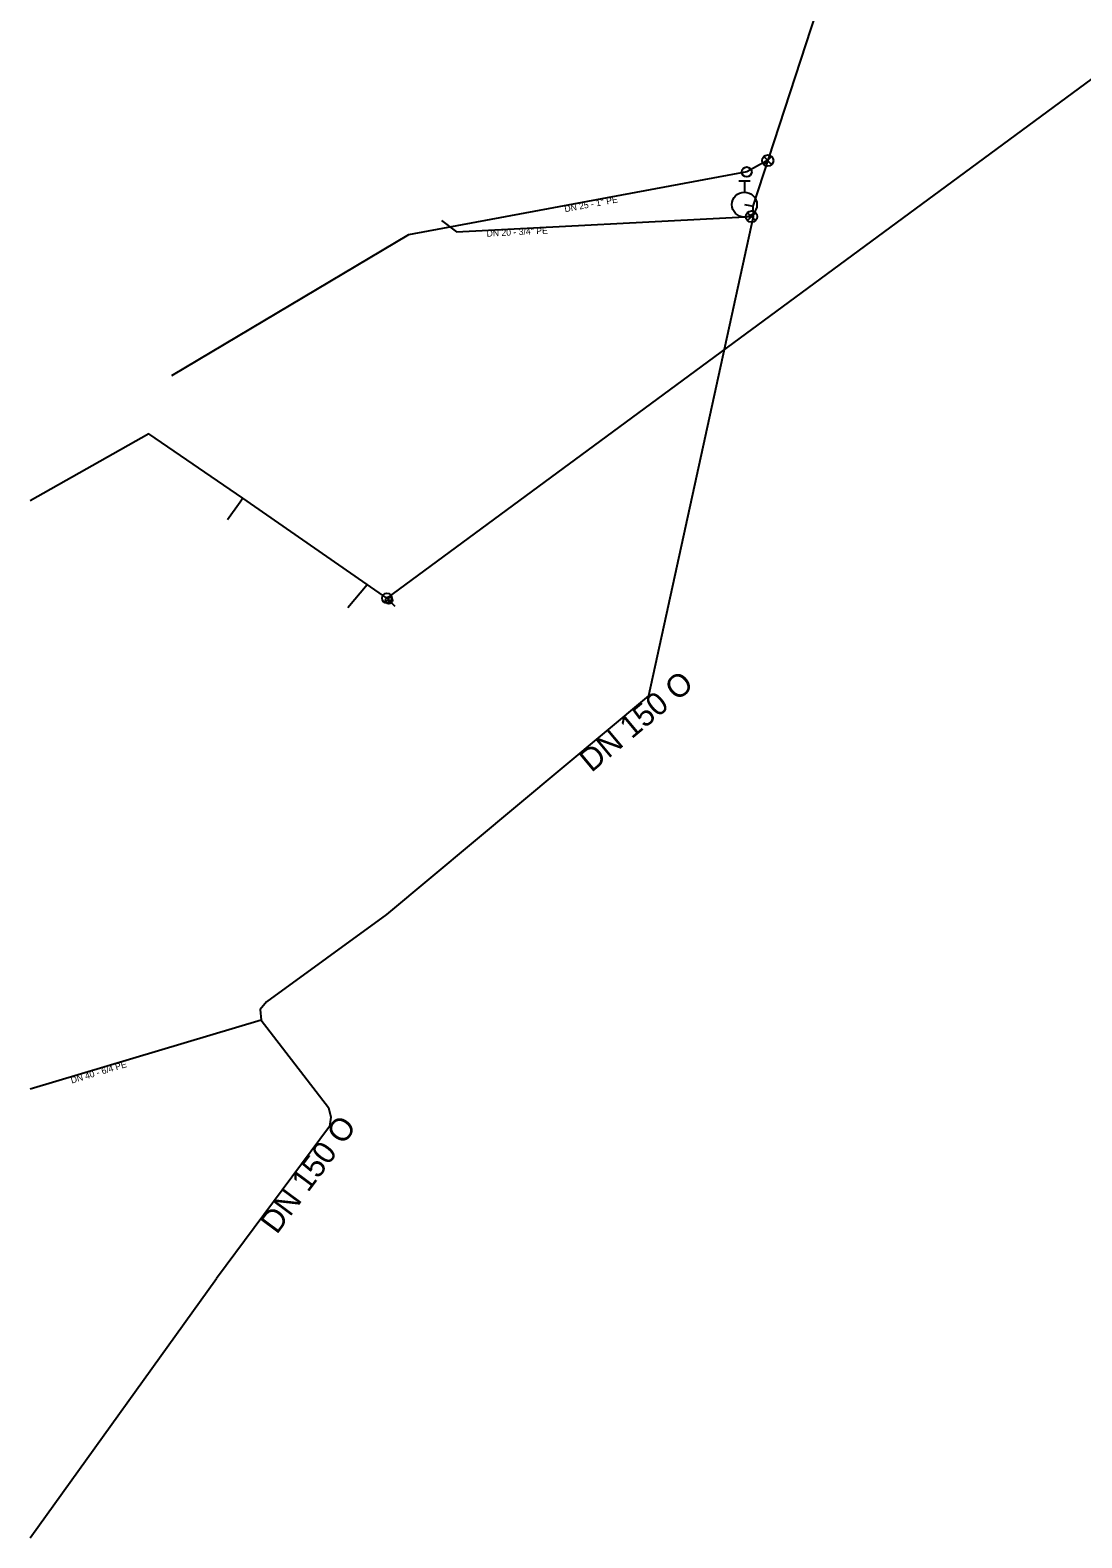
# Model space of a CAD drawing. Extents: x -451501 to -451094, y -1102108 to -1101623.
# Drawn here: x -451500.9 to -451426.7, y -1101844.7 to -1101738.2 of the extents above; entities that cross this region are included whole.
import ezdxf

# ---------------------------------------------------------------- set-up
doc = ezdxf.new("R2010")
doc.units = 0
for name, color, linetype in [('_hydrantova_odbocka_', 7, 'Continuous'), ('_kalosvod_', 7, 'Continuous'), ('_pripojka_prevzato_z_dokumentace_', 7, 'Continuous'), ('_pripojka_priblizne_', 7, 'Continuous'), ('_voda_smvak_prevzato_z_dokumentace_', 7, 'Continuous'), ('Default', 7, 'Continuous'), ('MoLevel 27', 7, 'Continuous'), ('MoLevel 28', 7, 'Continuous'), ('MoLevel 30', 7, 'Continuous'), ('MoLevel 32', 7, 'Continuous'), ('MoLevel 46', 7, 'Continuous'), ('MoLevel 53', 7, 'Continuous'), ('MoLevel 55', 7, 'Continuous')]:
    doc.layers.add(name, color=color, linetype=linetype)

# ---------------------------------------------------------------- blocks, each defined once
blk = doc.blocks.new('_uzaver_')
at = {"layer": 'Default'}
for p, q in [((-0.000035, -0.000035), (0.000035, 0.000035)), ((0.000035, -0.000035), (-0.000035, 0.000035))]:
    blk.add_line(p, q, dxfattribs=at)
for radius in [0.00005, 0.0000025]:
    blk.add_circle((0, 0), radius, dxfattribs=at)
blk = doc.blocks.new('_uzaver_pripojka_')
at = {"layer": 'Default'}
for p, q in [((-0.000035, -0.000035), (0.000035, 0.000035)), ((0.000035, -0.000035), (-0.000035, 0.000035))]:
    blk.add_line(p, q, dxfattribs=at)
for radius in [0.00005, 0.0000025]:
    blk.add_circle((0, 0), radius, dxfattribs=at)
blk = doc.blocks.new('_hydrant_voda_')
at = {"layer": 'Default'}
for p, q in [((-0.0000225, 0.000095), (0.0000225, 0.000095)), ((0, 0.000095), (0, 0.00005))]:
    blk.add_line(p, q, dxfattribs=at)
blk.add_circle((0, 0), 0.00005, dxfattribs=at)
blk = doc.blocks.new('_sachta_voda_')
at = {"layer": 'Default'}
blk.add_circle((0, 0), 0.000035, dxfattribs=at)

msp = doc.modelspace()

# ---------------------------------------------------------------- linework, layer by layer
at = {"layer": '_hydrantova_odbocka_'}
msp.add_lwpolyline([(-451450.48, -1101750.51), (-451450.11, -1101750.58), (-451449.89, -1101750.62)], dxfattribs=at)
at = {"layer": '_kalosvod_'}
msp.add_lwpolyline([(-451475.73, -1101778.32), (-451475.59, -1101778.47), (-451475.18, -1101778.88)], dxfattribs=at)
at = {"layer": '_pripojka_prevzato_z_dokumentace_'}
msp.add_line((-451484.62, -1101808.13), (-451500.93, -1101813.02), dxfattribs=at)
for points in [[(-451471.88, -1101751.64), (-451470.82, -1101752.43), (-451449.98, -1101751.36), (-451449.86, -1101751.37)], [(-451485.91, -1101771.25), (-451486.11, -1101771.53), (-451487, -1101772.78)]]:
    msp.add_lwpolyline(points, dxfattribs=at)
at = {"layer": '_pripojka_priblizne_'}
msp.add_line((-451478.49, -1101778.98), (-451477.13, -1101777.35), dxfattribs=at)
for points in [[(-451448.84, -1101747.4), (-451448.94, -1101747.44), (-451450.32, -1101748.2), (-451450.32, -1101748.2)], [(-451450.32, -1101748.2), (-451474.22, -1101752.65), (-451490.96, -1101762.62)], [(-451475.73, -1101778.32), (-451485.91, -1101771.25), (-451492.54, -1101766.7), (-451500.93, -1101771.44)]]:
    msp.add_lwpolyline(points, dxfattribs=at)
at = {"layer": '_voda_smvak_prevzato_z_dokumentace_'}
for p, q in [((-451391.04, -1101715.88), (-451475.73, -1101778.32)), ((-451500.93, -1101844.72), (-451487.78, -1101826.39))]:
    msp.add_line(p, q, dxfattribs=at)
for points in [[(-451352.37, -1101668.69), (-451374.89, -1101685.01), (-451391.64, -1101696.06), (-451420.33, -1101714.98), (-451434, -1101726.73), (-451445.03, -1101735.74), (-451449.89, -1101750.62)], [(-451449.89, -1101750.62), (-451449.86, -1101751.37), (-451457.26, -1101785.22), (-451475.77, -1101800.67), (-451484.25, -1101806.83), (-451484.69, -1101807.39), (-451484.62, -1101808.13)], [(-451484.62, -1101808.13), (-451479.87, -1101814.31), (-451479.69, -1101814.99), (-451479.8, -1101815.64), (-451487.78, -1101826.39)]]:
    msp.add_lwpolyline(points, dxfattribs=at)

# ---------------------------------------------------------------- block references
at = {"layer": 'MoLevel 27', "xscale": 5000, "yscale": 5000, "rotation": -37.40535663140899}
msp.add_blockref('_uzaver_', (-451475.59, -1101778.47), dxfattribs=at)
at = {"layer": 'MoLevel 28', "xscale": 17636.68430335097, "yscale": 17636.68430335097}
msp.add_blockref('_hydrant_voda_', (-451450.48, -1101750.51), dxfattribs=at)
at = {"layer": 'MoLevel 30', "xscale": 10000, "yscale": 10000}
for p in [(-451450.32, -1101748.2), (-451475.73, -1101778.32)]:
    msp.add_blockref('_sachta_voda_', p, dxfattribs=at)
at = {"layer": 'MoLevel 53', "xscale": 7999.999999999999, "yscale": 7999.999999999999}
for p in [(-451448.84, -1101747.4), (-451449.98, -1101751.36)]:
    msp.add_blockref('_uzaver_pripojka_', p, dxfattribs=at)

# ---------------------------------------------------------------- texts
at = {"layer": 'MoLevel 32'}
msp.add_text("DN 25 - 1'' PE", height=0.455, rotation=10.5549, dxfattribs=at).set_placement((-451463.15, -1101751.05))
at = {"layer": 'MoLevel 46'}
for rotation, p in [(39.8512, (-451461.29, -1101790.68)), (53.4126, (-451483.51, -1101823.33))]:
    msp.add_text('DN 150 O', height=1.605, rotation=rotation, dxfattribs=at).set_placement(p)
at = {"layer": 'MoLevel 55'}
for s, rotation, p in [("DN 20 - 3/4'' PE", 2.9392, (-451468.68, -1101752.78)), ('DN 40 - 6/4 PE', 16.7018, (-451497.99, -1101812.62))]:
    msp.add_text(s, height=0.455, rotation=rotation, dxfattribs=at).set_placement(p)

doc.saveas('drawing.dxf')
